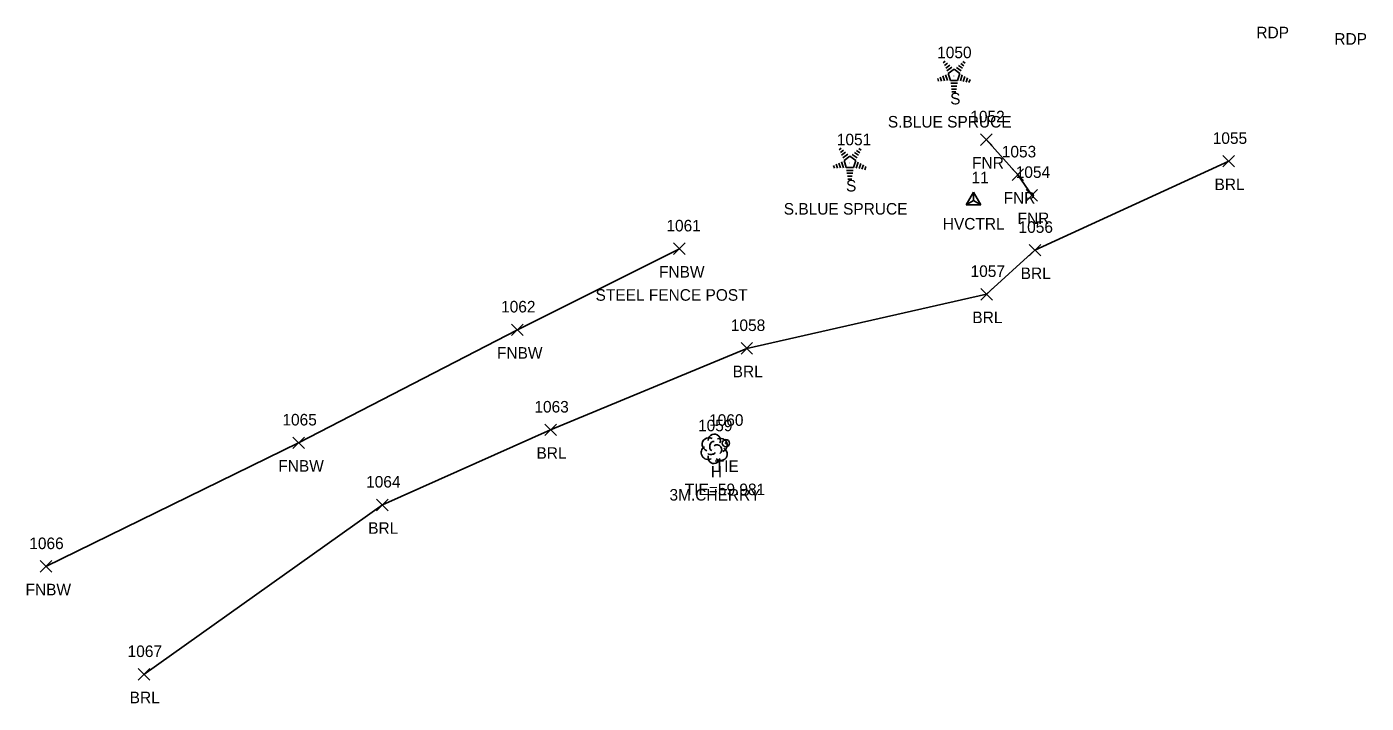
# Model space of a CAD drawing. Extents: x 1472022 to 1479249, y 777216 to 786527.
# Drawn here: x 1474006.3 to 1474238, y 779988.7 to 780105.8 of the extents above; entities that cross this region are included whole.
import ezdxf

# ---------------------------------------------------------------- set-up
doc = ezdxf.new("R2010")
doc.units = 0
for name, color, linetype in [('C_A', 7, 'Continuous'), ('C_C', 7, 'Continuous'), ('C_I', 7, 'Continuous'), ('CBP', 7, 'Continuous'), ('CPSM', 7, 'Continuous'), ('L_A', 7, 'Continuous'), ('L_C', 7, 'Continuous'), ('L_I', 7, 'Continuous'), ('L_TIC', 7, 'Continuous'), ('LABL', 7, 'Continuous'), ('LFNC', 7, 'Continuous'), ('LTC', 7, 'Continuous'), ('LTD', 7, 'Continuous'), ('P_A', 7, 'Continuous')]:
    doc.layers.add(name, color=color, linetype=linetype)

msp = doc.modelspace()

# ---------------------------------------------------------------- linework, layer by layer
at = {"layer": 'CBP'}
for radius in [0.625, 0.0833]:
    msp.add_circle((1474127.23, 780033.72), radius, dxfattribs=at)
at = {"layer": 'CPSM'}
for p, q in [((1474168.81, 780074.98), (1474170.06, 780077.15)), ((1474171.31, 780074.98), (1474170.06, 780077.15)), ((1474170.06, 780075.7), (1474170.06, 780077.15)), ((1474168.81, 780074.98), (1474170.06, 780075.7)), ((1474168.81, 780074.98), (1474171.31, 780074.98)), ((1474170.06, 780075.7), (1474170.06, 780075.7)), ((1474170.06, 780075.7), (1474171.31, 780074.98))]:
    msp.add_line(p, q, dxfattribs=at)
at = {"layer": 'L_TIC'}
for points in [[(1474171.28, 780085.25), (1474173.28, 780087.25)], [(1474173.28, 780085.25), (1474171.28, 780087.25)], [(1474213.22, 780081.52), (1474215.22, 780083.52)], [(1474215.22, 780081.52), (1474213.22, 780083.52)], [(1474176.73, 780079.18), (1474178.73, 780081.18)], [(1474178.73, 780079.18), (1474176.73, 780081.18)], [(1474179.15, 780075.63), (1474181.15, 780077.63)], [(1474181.15, 780075.63), (1474179.15, 780077.63)], [(1474118.19, 780066.37), (1474120.19, 780068.37)], [(1474120.19, 780066.37), (1474118.19, 780068.37)], [(1474179.69, 780066.12), (1474181.69, 780068.12)], [(1474181.69, 780066.12), (1474179.69, 780068.12)], [(1474171.33, 780058.49), (1474173.33, 780060.49)], [(1474173.33, 780058.49), (1474171.33, 780060.49)], [(1474090.16, 780052.34), (1474092.16, 780054.34)], [(1474092.16, 780052.34), (1474090.16, 780054.34)], [(1474129.86, 780049.13), (1474131.86, 780051.13)], [(1474131.86, 780049.13), (1474129.86, 780051.13)], [(1474095.91, 780035.02), (1474097.91, 780037.02)], [(1474097.91, 780035.02), (1474095.91, 780037.02)], [(1474052.32, 780032.78), (1474054.32, 780034.78)], [(1474054.32, 780032.78), (1474052.32, 780034.78)], [(1474066.81, 780022.03), (1474068.81, 780024.03)], [(1474068.81, 780022.03), (1474066.81, 780024.03)], [(1474008.6, 780011.38), (1474010.6, 780013.38)], [(1474010.6, 780011.38), (1474008.6, 780013.38)], [(1474025.55, 779992.7), (1474027.55, 779994.7)], [(1474027.55, 779992.7), (1474025.55, 779994.7)]]:
    msp.add_lwpolyline(points, dxfattribs=at)
at = {"layer": 'LABL'}
msp.add_lwpolyline([(1474214.22, 780082.52), (1474180.69, 780067.12), (1474172.33, 780059.49), (1474130.86, 780050.13), (1474096.91, 780036.02), (1474067.81, 780023.03), (1474026.55, 779993.7)], dxfattribs=at)
at = {"layer": 'LFNC'}
for points in [[(1474172.28, 780086.25), (1474177.73, 780080.18), (1474180.15, 780076.63)], [(1474119.19, 780067.37), (1474091.16, 780053.34), (1474053.32, 780033.78), (1474009.6, 780012.38)]]:
    msp.add_lwpolyline(points, dxfattribs=at)
at = {"layer": 'LTC'}
for p, q in [((1474164.83, 780099.56), (1474165.19, 780099.82)), ((1474168.23, 780099.8), (1474168.65, 780099.49)), ((1474164.78, 780097.27), (1474165.05, 780096.44)), ((1474165.04, 780099.09), (1474165.57, 780099.48)), ((1474165.23, 780097.49), (1474165.56, 780096.47)), ((1474165.25, 780098.63), (1474165.96, 780099.14)), ((1474165.46, 780098.16), (1474166.34, 780098.8)), ((1474165.69, 780097.71), (1474166.7, 780098.44)), ((1474165.69, 780097.71), (1474166.07, 780096.51)), ((1474166.7, 780098.44), (1474167.7, 780097.72)), ((1474167.12, 780098.75), (1474167.93, 780098.17)), ((1474167.7, 780097.72), (1474167.3, 780096.51)), ((1474167.49, 780099.1), (1474168.17, 780098.61)), ((1474168.13, 780097.45), (1474167.79, 780096.41)), ((1474167.86, 780099.45), (1474168.41, 780099.05)), ((1474163.87, 780096.84), (1474164.02, 780096.37)), ((1474164.32, 780097.05), (1474164.53, 780096.4)), ((1474167.3, 780096.51), (1474166.07, 780096.51)), ((1474167.27, 780096.01), (1474166.12, 780096.01)), ((1474167.18, 780095.51), (1474166.19, 780095.51)), ((1474167.1, 780095.01), (1474166.27, 780095.01)), ((1474168.58, 780097.2), (1474168.29, 780096.31)), ((1474169.02, 780096.95), (1474168.78, 780096.22)), ((1474169.47, 780096.69), (1474169.28, 780096.12)), ((1474167.01, 780094.51), (1474166.34, 780094.51)), ((1474146.82, 780084.49), (1474147.17, 780084.75)), ((1474147.03, 780084.02), (1474147.56, 780084.41)), ((1474147.24, 780083.56), (1474147.94, 780084.07)), ((1474147.45, 780083.09), (1474148.32, 780083.73)), ((1474147.67, 780082.64), (1474148.68, 780083.37)), ((1474148.68, 780083.37), (1474149.68, 780082.65)), ((1474149.1, 780083.69), (1474149.91, 780083.1)), ((1474149.47, 780084.03), (1474150.15, 780083.54)), ((1474149.84, 780084.38), (1474150.39, 780083.98)), ((1474150.21, 780084.73), (1474150.63, 780084.43)), ((1474145.85, 780081.77), (1474146, 780081.3)), ((1474146.3, 780081.99), (1474146.52, 780081.33)), ((1474146.76, 780082.2), (1474147.03, 780081.37)), ((1474147.22, 780082.42), (1474147.55, 780081.4)), ((1474147.67, 780082.64), (1474148.06, 780081.44)), ((1474149.29, 780081.44), (1474148.06, 780081.44)), ((1474149.68, 780082.65), (1474149.29, 780081.44)), ((1474150.12, 780082.38), (1474149.78, 780081.34)), ((1474150.56, 780082.13), (1474150.27, 780081.24)), ((1474151.01, 780081.88), (1474150.77, 780081.15)), ((1474151.45, 780081.63), (1474151.26, 780081.05)), ((1474149.25, 780080.94), (1474148.1, 780080.94)), ((1474149.17, 780080.44), (1474148.18, 780080.44)), ((1474149.08, 780079.94), (1474148.25, 780079.94)), ((1474149, 780079.44), (1474148.32, 780079.44))]:
    msp.add_line(p, q, dxfattribs=at)
at = {"layer": 'LTD'}
msp.add_line((1474125.19, 780032.78), (1474125.19, 780032.78), dxfattribs=at)
msp.add_line((1474125.19, 780032.78), (1474125.19, 780032.78), dxfattribs=at)
msp.add_arc((1474125.23, 780034.22), 1.05, 335.5272, 180.9563, dxfattribs=at)
for centre, major_axis, ratio, start_param, end_param in [((1474124.4, 780033.45), (1.21, -0.51), 0.895232, 1.570796, 4.712389), ((1474126.23, 780033.36), (-1.14, -0.48), 0.949671, 1.570796, 4.712389), ((1474124.1, 780032.07), (0.58, -1.04), 0.959034, 3.141593, 6.283185), ((1474124.98, 780033.24), (-0.208, -0.792), 0.645439, 3.141593, 6.283185), ((1474125.69, 780032.61), (-0.5, 0.667), 0.989748, 3.141593, 6.283185), ((1474126.19, 780031.95), (-1.09, 0.79), 0.841452, 1.570796, 4.712389), ((1474125.19, 780031.28), (0.26, 1.06), 0.942809, 1.570796, 4.712389), ((1474124.73, 780032.03), (-0.625, -0.083), 0.423636, 0, 3.141593)]:
    msp.add_ellipse(centre, major_axis=major_axis, ratio=ratio, start_param=start_param, end_param=end_param, dxfattribs=at)

# ---------------------------------------------------------------- texts
at = {"layer": 'C_A'}
for s, p in [('HVCTRL', (1474164.75, 780070.7)), ('TIE', (1474125.3, 780028.72))]:
    msp.add_text(s, height=2, dxfattribs=at).set_placement(p)
at = {"layer": 'C_C'}
msp.add_text('TIE=59.981', height=2, dxfattribs=at).set_placement((1474120.12, 780024.72))
at = {"layer": 'C_I'}
for s, p in [('11', (1474169.73, 780078.7)), ('1060', (1474124.32, 780036.72))]:
    msp.add_text(s, height=2, dxfattribs=at).set_placement(p)
at = {"layer": 'L_A'}
for s, p in [('S', (1474166.02, 780092.35)), ('FNR', (1474169.82, 780081.25)), ('S', (1474148.01, 780077.28)), ('BRL', (1474211.76, 780077.52)), ('FNR', (1474175.27, 780075.18)), ('FNR', (1474177.68, 780071.63)), ('FNBW', (1474115.66, 780062.37)), ('BRL', (1474178.23, 780062.12)), ('BRL', (1474169.87, 780054.49)), ('FNBW', (1474087.63, 780048.34)), ('BRL', (1474128.4, 780045.13)), ('BRL', (1474094.46, 780031.02)), ('FNBW', (1474049.8, 780028.78)), ('H', (1474124.62, 780027.78)), ('BRL', (1474065.35, 780018.03)), ('FNBW', (1474006.07, 780007.38)), ('BRL', (1474024.09, 779988.7))]:
    msp.add_text(s, height=2, dxfattribs=at).set_placement(p)
at = {"layer": 'L_C'}
for s, p in [('S.BLUE SPRUCE', (1474155.25, 780088.35)), ('S.BLUE SPRUCE', (1474137.24, 780073.28)), ('STEEL FENCE POST', (1474104.68, 780058.37)), ('3M.CHERRY', (1474117.47, 780023.78))]:
    msp.add_text(s, height=2, dxfattribs=at).set_placement(p)
at = {"layer": 'L_I'}
for s, p in [('1050', (1474163.78, 780100.35)), ('1052', (1474169.51, 780089.25)), ('1051', (1474146.42, 780085.28)), ('1055', (1474211.45, 780085.52)), ('1053', (1474174.96, 780083.18)), ('1054', (1474177.37, 780079.63)), ('1061', (1474116.94, 780070.37)), ('1056', (1474177.86, 780070.12)), ('1057', (1474169.56, 780062.49)), ('1062', (1474088.34, 780056.34)), ('1058', (1474128.09, 780053.13)), ('1063', (1474094.1, 780039.02)), ('1065', (1474050.51, 780036.78)), ('1059', (1474122.41, 780035.78)), ('1064', (1474064.99, 780026.03)), ('1066', (1474006.72, 780015.38)), ('1067', (1474023.73, 779996.7))]:
    msp.add_text(s, height=2, dxfattribs=at).set_placement(p)
at = {"layer": 'LTC'}
for p in [(1474166.58, 780097.45), (1474148.56, 780082.39)]:
    msp.add_text('.', height=1.04, rotation=270, dxfattribs=at).set_placement(p)
at = {"layer": 'P_A'}
for p in [(1474219, 780103.79), (1474232.49, 780102.69)]:
    msp.add_text('RDP', height=2, dxfattribs=at).set_placement(p)

doc.saveas('drawing.dxf')
